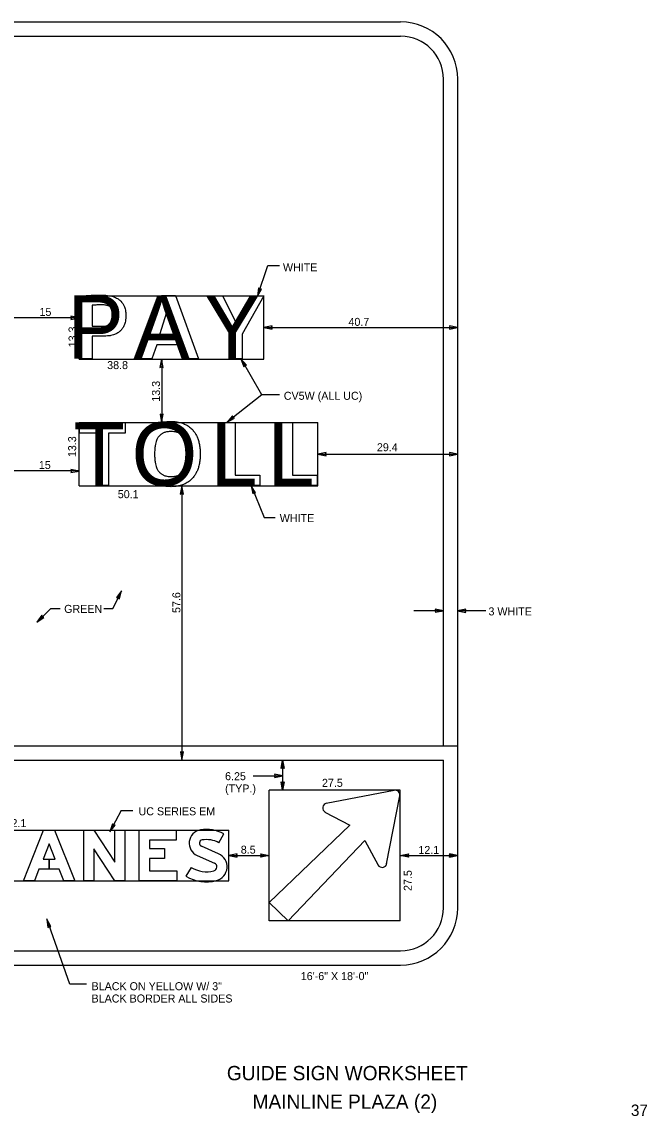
# Model space of a CAD drawing. Extents: x 319706 to 320019, y 1621790 to 1621996.
# Drawn here: x 319909.6 to 320019, y 1621795.1 to 1621986.5 of the extents above; entities that cross this region are included whole.
import ezdxf

# ---------------------------------------------------------------- set-up
doc = ezdxf.new("R2010")
doc.units = 0
for name, color, linetype in [('1', 7, 'Continuous'), ('48', 7, 'Continuous'), ('52', 7, 'Continuous'), ('GSBWFill', 7, 'Continuous'), ('GSColorFill', 7, 'Continuous'), ('GSOutline', 7, 'Continuous'), ('SOILS_SP83_SHP', 7, 'Continuous'), ('TextMisc', 7, 'Continuous'), ('TextShtNo', 7, 'Continuous')]:
    doc.layers.add(name, color=color, linetype=linetype)

msp = doc.modelspace()

# ---------------------------------------------------------------- linework, layer by layer
at = {"layer": '1'}
for p, q in [((319815.88, 1621986.54), (319975.88, 1621986.54)), ((319815.88, 1621984.04), (319975.88, 1621984.04)), ((319983.38, 1621859.87), (319983.38, 1621976.54)), ((319985.88, 1621831.54), (319985.88, 1621976.54)), ((319919.63, 1621938.62), (319951.96, 1621938.62)), ((319919.63, 1621927.54), (319919.63, 1621938.62)), ((319951.96, 1621927.54), (319951.96, 1621938.62)), ((319919.63, 1621927.54), (319951.96, 1621927.54)), ((319919.63, 1621905.37), (319919.63, 1621916.46)), ((319919.63, 1621916.46), (319961.38, 1621916.46)), ((319961.38, 1621905.37), (319961.38, 1621916.46)), ((319919.63, 1621905.37), (319961.38, 1621905.37)), ((319846.29, 1621859.87), (319985.88, 1621859.87)), ((319848.79, 1621857.37), (319983.38, 1621857.37)), ((319983.38, 1621831.54), (319983.38, 1621857.37)), ((319975.79, 1621852.16), (319952.88, 1621852.16)), ((319952.88, 1621829.25), (319952.88, 1621852.16)), ((319975.79, 1621829.25), (319975.79, 1621852.16)), ((319902.38, 1621845.16), (319945.79, 1621845.16)), ((319945.79, 1621836.27), (319945.79, 1621845.16)), ((319902.38, 1621836.27), (319945.79, 1621836.27)), ((319975.79, 1621829.25), (319952.88, 1621829.25)), ((319848.79, 1621824.04), (319975.88, 1621824.04)), ((319815.88, 1621821.54), (319975.88, 1621821.54))]:
    msp.add_line(p, q, dxfattribs=at)
for centre, radius, start, end in [((319975.88, 1621976.54), 10, 0, 90), ((319975.88, 1621976.54), 7.5, 0, 90), ((319975.88, 1621831.54), 10, 270, 360), ((319975.88, 1621831.54), 7.5, 270, 360)]:
    msp.add_arc(centre, radius, start, end, dxfattribs=at)
at = {"layer": '48'}
for p, q in [((319950.81, 1621938.54), (319952.65, 1621943.9)), ((319952.65, 1621943.9), (319954.67, 1621943.9)), ((319919.63, 1621934.78), (319907.13, 1621934.78)), ((319951.96, 1621933.08), (319985.88, 1621933.08)), ((319934.05, 1621927.54), (319934.05, 1621916.46)), ((319951.56, 1621921.3), (319947.94, 1621927.61)), ((319951.56, 1621921.3), (319945.51, 1621916.54)), ((319954.65, 1621921.3), (319951.56, 1621921.3)), ((319961.38, 1621910.92), (319985.88, 1621910.92)), ((319919.63, 1621907.98), (319907.13, 1621907.98)), ((319937.59, 1621905.37), (319937.59, 1621857.37)), ((319949.71, 1621905.42), (319951.98, 1621899.86)), ((319951.98, 1621899.86), (319953.94, 1621899.86)), ((319925.52, 1621883.92), (319927.06, 1621887.03)), ((319914.65, 1621883.92), (319912.24, 1621881.53)), ((319914.65, 1621883.92), (319916.3, 1621883.92)), ((319923.95, 1621883.92), (319925.52, 1621883.92)), ((319978.21, 1621883.55), (319983.38, 1621883.55)), ((319985.88, 1621883.55), (319990.82, 1621883.55)), ((319955.24, 1621852.16), (319955.24, 1621857.37)), ((319950.05, 1621854.64), (319955.26, 1621854.64)), ((319926.95, 1621848.59), (319924.99, 1621844.87)), ((319926.95, 1621848.59), (319929.03, 1621848.59)), ((319945.79, 1621840.71), (319952.88, 1621840.71)), ((319975.79, 1621840.71), (319985.88, 1621840.71)), ((319917.95, 1621818.18), (319913.95, 1621829.6)), ((319920.87, 1621818.18), (319917.95, 1621818.18))]:
    msp.add_line(p, q, dxfattribs=at)
at = {"layer": '52'}
for p, q in [((319951.02, 1621939.99), (319950.8, 1621938.53)), ((319950.8, 1621938.53), (319951.54, 1621939.81)), ((319951.24, 1621939.79), (319951.02, 1621939.99)), ((319951.54, 1621939.81), (319951.24, 1621939.79)), ((319919.61, 1621934.76), (319918.16, 1621935.04)), ((319918.16, 1621935.04), (319918.27, 1621934.76)), ((319918.27, 1621934.76), (319918.16, 1621934.49)), ((319918.16, 1621934.49), (319919.61, 1621934.76)), ((319953.41, 1621933.35), (319951.96, 1621933.08)), ((319951.96, 1621933.08), (319953.41, 1621932.8)), ((319953.3, 1621933.08), (319953.41, 1621933.35)), ((319953.41, 1621932.8), (319953.3, 1621933.08)), ((319985.86, 1621933.06), (319984.41, 1621933.34)), ((319984.41, 1621933.34), (319984.52, 1621933.06)), ((319984.52, 1621933.06), (319984.41, 1621932.79)), ((319984.41, 1621932.79), (319985.86, 1621933.06)), ((319934.03, 1621927.52), (319933.75, 1621926.07)), ((319934.3, 1621926.07), (319934.03, 1621927.52)), ((319947.93, 1621927.59), (319948.41, 1621926.2)), ((319948.89, 1621926.47), (319947.93, 1621927.59)), ((319933.75, 1621926.07), (319934.03, 1621926.18)), ((319934.03, 1621926.18), (319934.3, 1621926.07)), ((319948.41, 1621926.2), (319948.6, 1621926.43)), ((319948.6, 1621926.43), (319948.89, 1621926.47)), ((319934.03, 1621917.78), (319933.76, 1621917.89)), ((319933.76, 1621917.89), (319934.03, 1621916.44)), ((319934.03, 1621916.44), (319934.31, 1621917.89)), ((319934.31, 1621917.89), (319934.03, 1621917.78)), ((319946.47, 1621917.63), (319945.5, 1621916.52)), ((319945.5, 1621916.52), (319946.81, 1621917.2)), ((319946.56, 1621917.35), (319946.47, 1621917.63)), ((319946.81, 1621917.2), (319946.56, 1621917.35)), ((319962.83, 1621911.19), (319961.38, 1621910.92)), ((319961.38, 1621910.92), (319962.83, 1621910.64)), ((319962.72, 1621910.92), (319962.83, 1621911.19)), ((319962.83, 1621910.64), (319962.72, 1621910.92)), ((319985.86, 1621910.9), (319984.41, 1621911.18)), ((319984.41, 1621911.18), (319984.52, 1621910.9)), ((319984.52, 1621910.9), (319984.41, 1621910.63)), ((319984.41, 1621910.63), (319985.86, 1621910.9)), ((319919.61, 1621907.96), (319918.16, 1621908.24)), ((319918.16, 1621908.24), (319918.27, 1621907.96)), ((319918.27, 1621907.96), (319918.16, 1621907.69)), ((319918.16, 1621907.69), (319919.61, 1621907.96)), ((319937.59, 1621905.37), (319937.31, 1621903.92)), ((319937.86, 1621903.92), (319937.59, 1621905.37)), ((319949.71, 1621905.4), (319950, 1621903.95)), ((319950.5, 1621904.16), (319949.71, 1621905.4)), ((319937.31, 1621903.92), (319937.59, 1621904.03)), ((319937.59, 1621904.03), (319937.86, 1621903.92)), ((319950, 1621903.95), (319950.21, 1621904.16)), ((319950.21, 1621904.16), (319950.5, 1621904.16)), ((319927.04, 1621887.01), (319926.14, 1621885.84)), ((319926.14, 1621885.84), (319926.44, 1621885.81)), ((319926.44, 1621885.81), (319926.64, 1621885.6)), ((319926.64, 1621885.6), (319927.04, 1621887.01)), ((319983.36, 1621883.52), (319981.91, 1621883.8)), ((319981.91, 1621883.8), (319982.02, 1621883.52)), ((319982.02, 1621883.52), (319981.91, 1621883.25)), ((319981.91, 1621883.25), (319983.36, 1621883.52)), ((319987.31, 1621883.79), (319985.86, 1621883.52)), ((319985.86, 1621883.52), (319987.31, 1621883.24)), ((319987.2, 1621883.52), (319987.31, 1621883.79)), ((319987.31, 1621883.24), (319987.2, 1621883.52)), ((319913.06, 1621882.73), (319912.22, 1621881.51)), ((319912.22, 1621881.51), (319913.45, 1621882.33)), ((319913.17, 1621882.46), (319913.06, 1621882.73)), ((319913.45, 1621882.33), (319913.17, 1621882.46)), ((319937.59, 1621858.71), (319937.32, 1621858.82)), ((319937.32, 1621858.82), (319937.59, 1621857.37)), ((319937.59, 1621857.37), (319937.87, 1621858.82)), ((319937.87, 1621858.82), (319937.59, 1621858.71)), ((319954.96, 1621855.91), (319955.23, 1621857.36)), ((319955.23, 1621857.36), (319955.51, 1621855.91)), ((319955.24, 1621854.63), (319953.79, 1621854.91)), ((319953.79, 1621854.91), (319953.9, 1621854.63)), ((319953.9, 1621854.63), (319953.79, 1621854.36)), ((319953.79, 1621854.36), (319955.24, 1621854.63)), ((319955.23, 1621856.02), (319954.96, 1621855.91)), ((319955.51, 1621855.91), (319955.23, 1621856.02)), ((319955.22, 1621852.14), (319954.94, 1621853.59)), ((319954.94, 1621853.59), (319955.22, 1621853.48)), ((319955.22, 1621853.48), (319955.49, 1621853.59)), ((319955.49, 1621853.59), (319955.22, 1621852.14)), ((319925.42, 1621846.27), (319924.98, 1621844.86)), ((319924.98, 1621844.86), (319925.91, 1621846.01)), ((319925.61, 1621846.05), (319925.42, 1621846.27)), ((319925.91, 1621846.01), (319925.61, 1621846.05)), ((319947.24, 1621840.98), (319945.79, 1621840.71)), ((319945.79, 1621840.71), (319947.24, 1621840.43)), ((319947.13, 1621840.71), (319947.24, 1621840.98)), ((319947.24, 1621840.43), (319947.13, 1621840.71)), ((319951.54, 1621840.71), (319951.43, 1621840.98)), ((319951.43, 1621840.98), (319952.88, 1621840.71)), ((319952.88, 1621840.71), (319951.43, 1621840.43)), ((319951.43, 1621840.43), (319951.54, 1621840.71)), ((319975.78, 1621840.7), (319977.23, 1621840.98)), ((319977.23, 1621840.43), (319975.78, 1621840.7)), ((319977.23, 1621840.98), (319977.12, 1621840.7)), ((319977.12, 1621840.7), (319977.23, 1621840.43)), ((319985.86, 1621840.7), (319984.41, 1621840.98)), ((319984.41, 1621840.98), (319984.52, 1621840.7)), ((319984.52, 1621840.7), (319984.41, 1621840.43)), ((319984.41, 1621840.43), (319985.86, 1621840.7)), ((319984.54, 1621840.7), (319984.43, 1621840.97)), ((319984.43, 1621840.97), (319985.88, 1621840.7)), ((319985.88, 1621840.7), (319984.43, 1621840.42)), ((319984.43, 1621840.42), (319984.54, 1621840.7)), ((319913.93, 1621829.58), (319914.15, 1621828.12)), ((319914.67, 1621828.3), (319913.93, 1621829.58)), ((319914.15, 1621828.12), (319914.38, 1621828.31)), ((319914.38, 1621828.31), (319914.67, 1621828.3))]:
    msp.add_line(p, q, dxfattribs=at)
at = {"layer": 'GSBWFill'}
for p, q in [((319944.08, 1621842.94), (319944.92, 1621844.51)), ((319944.01, 1621841.01), (319941, 1621842.33)), ((319940.29, 1621840.7), (319943.3, 1621839.38)), ((319939.22, 1621838.63), (319938.3, 1621837.11))]:
    msp.add_line(p, q, dxfattribs=at)
for points in [[(319914.33, 1621840.08), (319914.33, 1621838.3), (319912.57, 1621838.3), (319911.76, 1621836.26), (319909.84, 1621836.26), (319913.38, 1621845.15), (319915.29, 1621845.15), (319918.82, 1621836.26), (319916.91, 1621836.26), (319916.1, 1621838.3), (319914.33, 1621838.3), (319914.33, 1621840.08), (319915.39, 1621840.08), (319914.33, 1621842.74), (319913.28, 1621840.08)], [(319920.43, 1621845.15), (319922.2, 1621845.15), (319925.85, 1621839.55), (319925.85, 1621845.15), (319927.63, 1621845.15), (319927.63, 1621836.26), (319925.87, 1621836.26), (319922.2, 1621841.89), (319922.2, 1621836.26), (319920.43, 1621836.26)], [(319936.61, 1621845.15), (319936.61, 1621843.37), (319931.9, 1621843.37), (319931.9, 1621841.95), (319934.56, 1621841.95), (319934.56, 1621840.17), (319931.9, 1621840.17), (319931.9, 1621838.03), (319936.7, 1621838.03), (319936.7, 1621836.26), (319930.12, 1621836.26), (319930.12, 1621845.15)]]:
    msp.add_lwpolyline(points, close=True, dxfattribs=at)
for centre, radius, start, end in [((319941.23, 1621842.86), 2.36, 99.4877, 246.3243), ((319941.9, 1621838.87), 6.4, 61.8214, 99.4877), ((319941.23, 1621842.86), 0.578, 99.4877, 246.3243), ((319941.9, 1621838.87), 4.62, 61.8214, 99.4877), ((319943.01, 1621838.73), 0.711, 284.4775, 66.3243), ((319943.01, 1621838.73), 2.49, 284.4775, 66.3243), ((319941.9, 1621843.03), 5.16, 238.7193, 284.4775), ((319941.9, 1621843.03), 6.94, 238.7193, 284.4775)]:
    msp.add_arc(centre, radius, start, end, dxfattribs=at)
at = {"layer": 'GSColorFill'}
for p, q in [((319944.08, 1621842.94), (319944.92, 1621844.51)), ((319944.01, 1621841.01), (319941, 1621842.33)), ((319940.29, 1621840.7), (319943.3, 1621839.38)), ((319939.22, 1621838.63), (319938.3, 1621837.11))]:
    msp.add_line(p, q, dxfattribs=at)
for points in [[(319914.33, 1621840.08), (319914.33, 1621838.3), (319912.57, 1621838.3), (319911.76, 1621836.26), (319909.84, 1621836.26), (319913.38, 1621845.15), (319915.29, 1621845.15), (319918.82, 1621836.26), (319916.91, 1621836.26), (319916.1, 1621838.3), (319914.33, 1621838.3), (319914.33, 1621840.08), (319915.39, 1621840.08), (319914.33, 1621842.74), (319913.28, 1621840.08)], [(319920.43, 1621845.15), (319922.2, 1621845.15), (319925.85, 1621839.55), (319925.85, 1621845.15), (319927.63, 1621845.15), (319927.63, 1621836.26), (319925.87, 1621836.26), (319922.2, 1621841.89), (319922.2, 1621836.26), (319920.43, 1621836.26)], [(319936.61, 1621845.15), (319936.61, 1621843.37), (319931.9, 1621843.37), (319931.9, 1621841.95), (319934.56, 1621841.95), (319934.56, 1621840.17), (319931.9, 1621840.17), (319931.9, 1621838.03), (319936.7, 1621838.03), (319936.7, 1621836.26), (319930.12, 1621836.26), (319930.12, 1621845.15)]]:
    msp.add_lwpolyline(points, close=True, dxfattribs=at)
for centre, radius, start, end in [((319941.23, 1621842.86), 2.36, 99.4877, 246.3243), ((319941.9, 1621838.87), 6.4, 61.8214, 99.4877), ((319941.23, 1621842.86), 0.578, 99.4877, 246.3243), ((319941.9, 1621838.87), 4.62, 61.8214, 99.4877), ((319943.01, 1621838.73), 0.711, 284.4775, 66.3243), ((319943.01, 1621838.73), 2.49, 284.4775, 66.3243), ((319941.9, 1621843.03), 5.16, 238.7193, 284.4775), ((319941.9, 1621843.03), 6.94, 238.7193, 284.4775)]:
    msp.add_arc(centre, radius, start, end, dxfattribs=at)
at = {"layer": 'GSOutline'}
for p, q in [((319944.08, 1621842.94), (319944.92, 1621844.51)), ((319944.01, 1621841.01), (319941, 1621842.33)), ((319940.29, 1621840.7), (319943.3, 1621839.38)), ((319939.22, 1621838.63), (319938.3, 1621837.11))]:
    msp.add_line(p, q, dxfattribs=at)
for points in [[(319923.99, 1621931.57), (319921.91, 1621931.57), (319921.91, 1621927.6), (319919.77, 1621927.6), (319919.77, 1621938.56)], [(319921.91, 1621936.98), (319921.91, 1621933.3), (319923.57, 1621933.3)], [(319938.17, 1621927.6), (319937.3, 1621930.03), (319933.2, 1621930.03), (319932.35, 1621927.6), (319930.09, 1621927.6), (319934.03, 1621938.68), (319936.46, 1621938.68), (319940.47, 1621927.6), (319938.17, 1621927.6)], [(319948.17, 1621931.92), (319948.17, 1621927.6), (319946.03, 1621927.6), (319946.03, 1621931.85), (319942.24, 1621938.64), (319944.67, 1621938.64), (319947.12, 1621933.77), (319949.58, 1621938.64), (319951.93, 1621938.64), (319948.17, 1621931.92)], [(319935.26, 1621936.62), (319935.2, 1621936.62), (319933.65, 1621931.8), (319936.82, 1621931.8), (319935.26, 1621936.62)], [(319924.76, 1621914.62), (319924.76, 1621905.42), (319922.6, 1621905.42), (319922.6, 1621914.62), (319919.69, 1621914.62), (319919.69, 1621916.46), (319927.67, 1621916.46), (319927.67, 1621914.62), (319924.76, 1621914.62)], [(319944.79, 1621905.42), (319944.79, 1621916.46), (319946.93, 1621916.46), (319946.93, 1621907.24), (319951.26, 1621907.24), (319951.26, 1621905.42), (319944.79, 1621905.42)], [(319954.8, 1621905.42), (319954.8, 1621916.46), (319956.95, 1621916.46), (319956.95, 1621907.24), (319961.27, 1621907.24), (319961.27, 1621905.42), (319954.8, 1621905.42)]]:
    msp.add_lwpolyline(points, dxfattribs=at)
for points in [[(319916.1, 1621838.3), (319912.57, 1621838.3), (319911.76, 1621836.26), (319909.84, 1621836.26), (319913.38, 1621845.15), (319915.29, 1621845.15), (319918.82, 1621836.26), (319916.91, 1621836.26)], [(319920.43, 1621845.15), (319922.2, 1621845.15), (319925.85, 1621839.55), (319925.85, 1621845.15), (319927.63, 1621845.15), (319927.63, 1621836.26), (319925.87, 1621836.26), (319922.2, 1621841.89), (319922.2, 1621836.26), (319920.43, 1621836.26)], [(319936.61, 1621845.15), (319936.61, 1621843.37), (319931.9, 1621843.37), (319931.9, 1621841.95), (319934.56, 1621841.95), (319934.56, 1621840.17), (319931.9, 1621840.17), (319931.9, 1621838.03), (319936.7, 1621838.03), (319936.7, 1621836.26), (319930.12, 1621836.26), (319930.12, 1621845.15)], [(319913.28, 1621840.08), (319915.39, 1621840.08), (319914.33, 1621842.74)]]:
    msp.add_lwpolyline(points, close=True, dxfattribs=at)
for centre, radius, start, end in [((319941.23, 1621842.86), 2.36, 99.4877, 246.3243), ((319941.9, 1621838.87), 6.4, 61.8214, 99.4877), ((319941.23, 1621842.86), 0.578, 99.4877, 246.3243), ((319941.9, 1621838.87), 4.62, 61.8214, 99.4877), ((319943.01, 1621838.73), 0.711, 284.4775, 66.3243), ((319943.01, 1621838.73), 2.49, 284.4775, 66.3243), ((319941.9, 1621843.03), 5.16, 238.7193, 284.4775), ((319941.9, 1621843.03), 6.94, 238.7193, 284.4775)]:
    msp.add_arc(centre, radius, start, end, dxfattribs=at)
for points in [[(319919.77, 1621938.56), (319920.03, 1621938.59), (319920.6, 1621938.64), (319921.49, 1621938.7), (319922.45, 1621938.74), (319923.1, 1621938.75), (319923.43, 1621938.75)], [(319923.43, 1621938.75), (319923.58, 1621938.75), (319924.01, 1621938.74), (319924.58, 1621938.69), (319925.13, 1621938.59), (319925.57, 1621938.48), (319925.99, 1621938.32), (319926.31, 1621938.14), (319926.52, 1621938.01), (319926.71, 1621937.87), (319926.93, 1621937.67), (319927.16, 1621937.4), (319927.33, 1621937.15), (319927.44, 1621936.93), (319927.55, 1621936.69), (319927.66, 1621936.37), (319927.76, 1621935.86), (319927.77, 1621935.47), (319927.78, 1621935.23)], [(319923.49, 1621937.03), (319923.37, 1621937.03), (319923.12, 1621937.03), (319922.73, 1621937.02), (319922.33, 1621937), (319922.06, 1621936.99), (319921.91, 1621936.98)], [(319925.6, 1621935.17), (319925.6, 1621935.26), (319925.6, 1621935.49), (319925.57, 1621935.79), (319925.51, 1621936.03), (319925.46, 1621936.17), (319925.4, 1621936.31), (319925.3, 1621936.45), (319925.21, 1621936.56), (319925.13, 1621936.63), (319925.04, 1621936.7), (319924.92, 1621936.78), (319924.75, 1621936.86), (319924.6, 1621936.91), (319924.44, 1621936.95), (319924.17, 1621937), (319923.84, 1621937.03), (319923.59, 1621937.03), (319923.49, 1621937.03)], [(319923.57, 1621933.3), (319923.72, 1621933.31), (319924.01, 1621933.31), (319924.32, 1621933.34), (319924.54, 1621933.38), (319924.69, 1621933.42), (319924.85, 1621933.48), (319924.97, 1621933.54), (319925.06, 1621933.6), (319925.15, 1621933.67), (319925.25, 1621933.77), (319925.35, 1621933.91), (319925.42, 1621934.05), (319925.47, 1621934.17), (319925.51, 1621934.3), (319925.57, 1621934.54), (319925.6, 1621934.84), (319925.6, 1621935.07), (319925.6, 1621935.17)], [(319927.78, 1621935.23), (319927.78, 1621935.09), (319927.77, 1621934.69), (319927.7, 1621934.18), (319927.58, 1621933.76), (319927.49, 1621933.48), (319927.37, 1621933.22), (319927.21, 1621932.93), (319927.04, 1621932.71), (319926.89, 1621932.54), (319926.73, 1621932.39), (319926.51, 1621932.21), (319926.21, 1621932.03), (319925.94, 1621931.91), (319925.65, 1621931.8), (319925.18, 1621931.66), (319924.6, 1621931.58), (319924.15, 1621931.58), (319923.99, 1621931.57)], [(319930.54, 1621910.95), (319930.55, 1621911.17), (319930.56, 1621911.79), (319930.67, 1621912.6), (319930.88, 1621913.35), (319931.04, 1621913.78), (319931.22, 1621914.18), (319931.43, 1621914.55), (319931.67, 1621914.9), (319931.89, 1621915.15), (319932.11, 1621915.38), (319932.42, 1621915.65), (319932.83, 1621915.93), (319933.2, 1621916.12), (319933.51, 1621916.26), (319933.83, 1621916.38), (319934.36, 1621916.52), (319935.01, 1621916.62), (319935.49, 1621916.63), (319935.69, 1621916.64)], [(319935.69, 1621916.64), (319935.89, 1621916.63), (319936.36, 1621916.62), (319937.02, 1621916.52), (319937.54, 1621916.38), (319937.87, 1621916.26), (319938.18, 1621916.12), (319938.54, 1621915.93), (319938.95, 1621915.65), (319939.25, 1621915.38), (319939.48, 1621915.15), (319939.69, 1621914.9), (319939.98, 1621914.48), (319940.26, 1621913.94), (319940.48, 1621913.35), (319940.68, 1621912.6), (319940.79, 1621911.79), (319940.8, 1621911.17), (319940.81, 1621910.95)], [(319935.68, 1621914.88), (319935.54, 1621914.88), (319935.34, 1621914.87), (319935.03, 1621914.83), (319934.74, 1621914.78), (319934.47, 1621914.68), (319934.28, 1621914.59), (319934.1, 1621914.49), (319933.89, 1621914.35), (319933.67, 1621914.15), (319933.51, 1621913.95), (319933.4, 1621913.78), (319933.29, 1621913.61), (319933.15, 1621913.31), (319933.03, 1621912.94), (319932.91, 1621912.41), (319932.83, 1621911.76), (319932.82, 1621911.22), (319932.81, 1621910.95)], [(319938.55, 1621910.95), (319938.55, 1621911.22), (319938.54, 1621911.76), (319938.45, 1621912.41), (319938.34, 1621912.94), (319938.21, 1621913.31), (319938.07, 1621913.61), (319937.97, 1621913.78), (319937.85, 1621913.95), (319937.69, 1621914.15), (319937.47, 1621914.35), (319937.26, 1621914.49), (319937.08, 1621914.59), (319936.89, 1621914.68), (319936.62, 1621914.77), (319936.2, 1621914.86), (319935.88, 1621914.87), (319935.68, 1621914.88)], [(319935.69, 1621905.23), (319935.49, 1621905.23), (319935.01, 1621905.25), (319934.37, 1621905.34), (319933.85, 1621905.49), (319933.52, 1621905.61), (319933.21, 1621905.74), (319932.84, 1621905.94), (319932.43, 1621906.22), (319932.13, 1621906.48), (319931.9, 1621906.72), (319931.68, 1621906.97), (319931.44, 1621907.31), (319931.14, 1621907.85), (319930.9, 1621908.44), (319930.67, 1621909.28), (319930.56, 1621910.1), (319930.55, 1621910.73), (319930.54, 1621910.95)], [(319932.81, 1621910.95), (319932.82, 1621910.66), (319932.83, 1621910.13), (319932.91, 1621909.47), (319933.03, 1621908.94), (319933.15, 1621908.57), (319933.29, 1621908.27), (319933.4, 1621908.1), (319933.51, 1621907.93), (319933.67, 1621907.73), (319933.9, 1621907.53), (319934.1, 1621907.39), (319934.28, 1621907.29), (319934.48, 1621907.2), (319934.75, 1621907.1), (319935.17, 1621907.02), (319935.49, 1621907.01), (319935.69, 1621907)], [(319935.69, 1621907), (319935.82, 1621907), (319936.02, 1621907.01), (319936.33, 1621907.05), (319936.62, 1621907.1), (319936.89, 1621907.2), (319937.08, 1621907.29), (319937.26, 1621907.39), (319937.47, 1621907.53), (319937.69, 1621907.74), (319937.85, 1621907.93), (319937.97, 1621908.1), (319938.07, 1621908.28), (319938.21, 1621908.58), (319938.34, 1621908.95), (319938.45, 1621909.48), (319938.54, 1621910.13), (319938.55, 1621910.67), (319938.55, 1621910.95)], [(319940.81, 1621910.95), (319940.8, 1621910.73), (319940.79, 1621910.1), (319940.68, 1621909.28), (319940.47, 1621908.52), (319940.25, 1621907.93), (319939.97, 1621907.39), (319939.67, 1621906.97), (319939.46, 1621906.72), (319939.23, 1621906.48), (319938.93, 1621906.22), (319938.52, 1621905.94), (319938.16, 1621905.74), (319937.85, 1621905.61), (319937.53, 1621905.49), (319937.01, 1621905.34), (319936.36, 1621905.25), (319935.88, 1621905.23), (319935.69, 1621905.23)]]:
    msp.add_open_spline(points, degree=3, dxfattribs=at)
at = {"layer": 'SOILS_SP83_SHP'}
for p, q in [((319974.75, 1621852.1), (319962.87, 1621849.8)), ((319973.43, 1621839.25), (319975.73, 1621851.13)), ((319962.64, 1621848.3), (319966.97, 1621846.02)), ((319966.97, 1621846.02), (319952.87, 1621832.51)), ((319956.19, 1621829.29), (319969.64, 1621843.34)), ((319969.64, 1621843.34), (319971.92, 1621839.02)), ((319952.87, 1621832.51), (319956.19, 1621829.29))]:
    msp.add_line(p, q, dxfattribs=at)
for centre, start, end in [((319974.93, 1621851.31), 349.1046, 100.893), ((319963.08, 1621849.03), 100.893, 241.9756), ((319972.65, 1621839.46), 208.0246, 349.1046)]:
    msp.add_arc(centre, 0.833, start, end, dxfattribs=at)

# ---------------------------------------------------------------- texts
at = {"layer": '48'}
for s, p in [('WHITE', (319955.28, 1621942.9)), ('15', (319912.66, 1621935.1)), ('40.7', (319966.75, 1621933.36)), ('38.8', (319924.51, 1621925.8)), ('CV5W (ALL UC)', (319955.43, 1621920.43)), ('29.4', (319971.73, 1621911.43)), ('15', (319912.55, 1621908.32)), ('50.1', (319926.37, 1621903.22)), ('WHITE', (319954.72, 1621899.03)), ('GREEN', (319916.98, 1621883.15)), ('3 WHITE', (319991.26, 1621882.71)), ('6.25', (319945.15, 1621853.88)), ('(TYP.)', (319945.15, 1621851.73)), ('27.5', (319962.11, 1621852.72)), ('UC SERIES EM', (319930, 1621847.74)), ('52.1', (319906.72, 1621845.67)), ('8.5', (319947.9, 1621841.03)), ('12.1', (319978.99, 1621840.98)), ('16\'-6" X 18\'-0"', (319958.4, 1621818.91)), ('BLACK ON YELLOW W/ 3"', (319921.78, 1621817.14)), ('BLACK BORDER ALL SIDES', (319921.78, 1621814.99))]:
    msp.add_text(s, height=1.4, dxfattribs=at).set_placement(p)
for s, p in [('13.3', (319919.15, 1621929.61)), ('13.3', (319933.75, 1621920.09)), ('13.3', (319919.08, 1621910.4)), ('57.6', (319937.32, 1621883.13)), ('27.5', (319977.83, 1621834.5))]:
    msp.add_text(s, height=1.4, rotation=90, dxfattribs=at).set_placement(p)
at = {"layer": 'GSBWFill'}
for s, p in [('P', (319917.55, 1621927.6)), ('A', (319929.1, 1621927.6)), ('Y', (319941.46, 1621927.6)), ('T', (319918.58, 1621905.42)), ('O', (319928.77, 1621905.42)), ('L', (319942.57, 1621905.42)), ('L', (319952.58, 1621905.42))]:
    msp.add_text(s, height=11.08, dxfattribs=at).set_placement(p)
at = {"layer": 'GSColorFill'}
for s, p in [('P', (319917.55, 1621927.6)), ('A', (319929.1, 1621927.6)), ('Y', (319941.46, 1621927.6)), ('T', (319918.58, 1621905.42)), ('O', (319928.77, 1621905.42)), ('L', (319942.57, 1621905.42)), ('L', (319952.58, 1621905.42))]:
    msp.add_text(s, height=11.08, dxfattribs=at).set_placement(p)
at = {"layer": 'TextMisc'}
for s, p in [('  GUIDE SIGN WORKSHEET  ', (319943.6, 1621801.39)), ('   MAINLINE PLAZA (2)   ', (319947.18, 1621796.39))]:
    msp.add_text(s, height=2.5, rotation=360, dxfattribs=at).set_placement(p)
at = {"layer": 'TextShtNo'}
msp.add_text('37', height=2, rotation=360, dxfattribs=at).set_placement((320016.19, 1621795.14))

doc.saveas('drawing.dxf')
